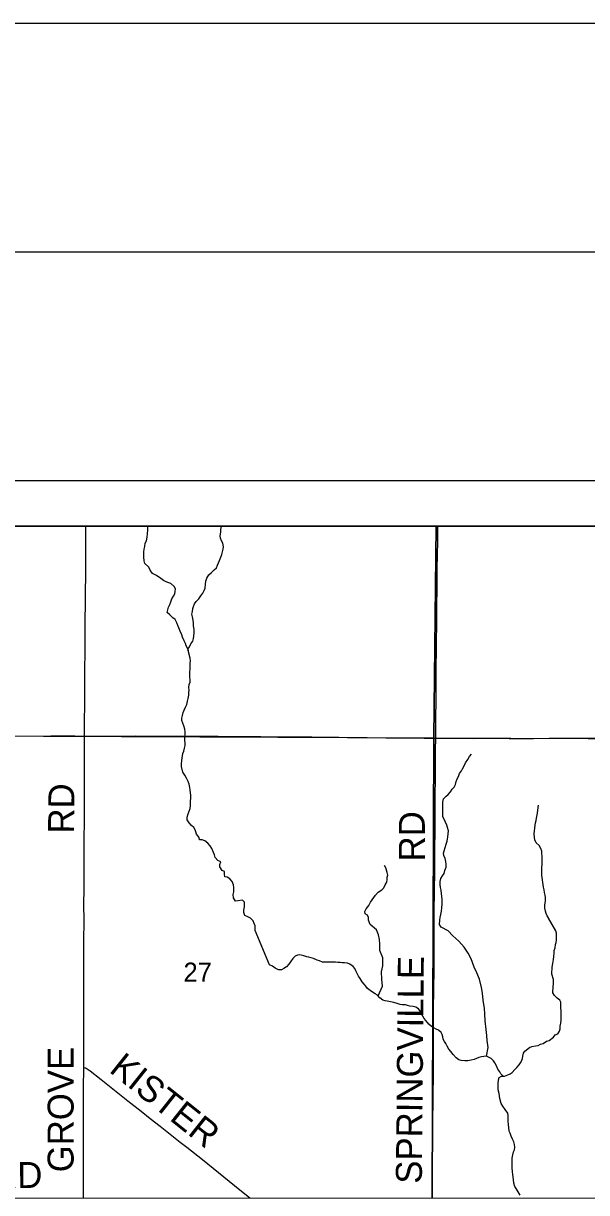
# Model space of a CAD drawing. Extents: x 0 to 34, y 0 to 22.
# Drawn here: x 6.615 to 7.847, y 19.442 to 22 of the extents above; entities that cross this region are included whole.
import ezdxf

# ---------------------------------------------------------------- set-up
doc = ezdxf.new("R2010")
doc.units = 0
for name, color, linetype in [('Default', 7, 'Continuous'), ('GM_X_County_Road', 7, 'Continuous'), ('GM_X_County_Road_Text', 7, 'Continuous'), ('GM_X_Minor_River', 7, 'Continuous'), ('GM_X_Section', 7, 'Continuous'), ('GM_X_Section_Text', 7, 'Continuous'), ('GM_X_Township_Road', 7, 'Continuous'), ('GM_X_Township_Road_Text', 7, 'Continuous'), ('SH_Border', 7, 'Continuous'), ('SH_Cut_Line', 7, 'Continuous'), ('SH_Data', 7, 'Continuous')]:
    doc.layers.add(name, color=color, linetype=linetype)

msp = doc.modelspace()

# ---------------------------------------------------------------- linework, layer by layer
at = {"layer": 'Default'}
msp.add_lwpolyline([(6.4755, 18.4174), (6.6827, 18.4182), (7.4947, 18.4149), (8.508, 18.4199), (8.7888, 18.4255), (8.8212, 18.4259), (8.9, 18.4271), (8.9, 20.9), (2.6032, 20.9)], dxfattribs=at)
for points in [[(7.5179, 20.9), (6.4922, 20.9), (6.4874, 20.4413), (7.5127, 20.4367)], [(8.5341, 20.9), (7.5179, 20.9), (7.5127, 20.4367), (8.5257, 20.4329)]]:
    msp.add_lwpolyline(points, close=True, dxfattribs=at)
at = {"layer": 'GM_X_County_Road'}
for points in [[(6.7486, 20.4407), (6.7487, 20.4682), (6.749, 20.515), (6.7495, 20.5555), (6.7498, 20.655), (6.7499, 20.6735), (6.7503, 20.7045), (6.7505, 20.72), (6.7509, 20.7542), (6.7514, 20.7946), (6.7515, 20.813), (6.7517, 20.8275), (6.7517, 20.8473), (6.7515, 20.8628), (6.7515, 20.8939), (6.7516, 20.9)], [(6.747, 19.7154), (6.747, 19.7232), (6.7474, 19.7542), (6.7472, 19.7698), (6.7471, 19.8029), (6.7471, 19.8471), (6.7473, 19.912), (6.7474, 19.9371), (6.7473, 19.9994), (6.7475, 20.0304), (6.7474, 20.0802), (6.7475, 20.0988), (6.7477, 20.1484), (6.7479, 20.1826), (6.748, 20.2005), (6.7481, 20.2197), (6.7483, 20.2504), (6.7486, 20.2831), (6.7484, 20.3187), (6.7484, 20.3407), (6.7484, 20.3627), (6.7484, 20.3968), (6.7485, 20.4156), (6.7486, 20.4407)], [(6.7466, 19.4306), (6.7466, 19.4363), (6.7466, 19.4747), (6.7467, 19.4996), (6.7467, 19.5338), (6.7467, 19.5647), (6.7465, 19.6145), (6.7467, 19.6702), (6.747, 19.7154)]]:
    msp.add_lwpolyline(points, dxfattribs=at)
at = {"layer": 'GM_X_Minor_River'}
for points in [[(6.9797, 20.6116), (6.9766, 20.6222), (6.9758, 20.6271), (6.9735, 20.6332), (6.9708, 20.6385), (6.9693, 20.6435), (6.9666, 20.6495), (6.9627, 20.6575), (6.9612, 20.6624), (6.9577, 20.6704), (6.955, 20.6776), (6.9524, 20.6829), (6.9504, 20.6886), (6.947, 20.6955), (6.942, 20.6996), (6.9352, 20.706), (6.9294, 20.7113), (6.9305, 20.7167), (6.9324, 20.7228), (6.935, 20.7289), (6.9377, 20.7342), (6.9399, 20.741), (6.9433, 20.7468), (6.9459, 20.7517), (6.947, 20.757), (6.9474, 20.7631), (6.9447, 20.7684), (6.9375, 20.7749), (6.931, 20.7771), (6.926, 20.779), (6.9211, 20.7813), (6.9158, 20.7854), (6.9062, 20.7918), (6.8975, 20.7967), (6.8925, 20.8039), (6.8891, 20.81), (6.8807, 20.8187), (6.8791, 20.8244), (6.8783, 20.832), (6.8783, 20.8392), (6.8786, 20.8442), (6.8794, 20.8495), (6.8805, 20.8556), (6.8816, 20.8628), (6.8838, 20.8682), (6.8853, 20.8758), (6.8864, 20.883), (6.8871, 20.8917), (6.8871, 20.8967), (6.8868, 20.9)], [(6.9797, 20.6116), (6.9743, 20.6309), (6.9784, 20.6359), (6.981, 20.6428), (6.9852, 20.6485), (6.9867, 20.6546), (6.9874, 20.6595), (6.9885, 20.6671), (6.9881, 20.674), (6.9873, 20.6823), (6.9869, 20.6876), (6.9861, 20.6945), (6.9845, 20.7017), (6.9837, 20.7078), (6.9845, 20.7131), (6.9856, 20.7196), (6.9871, 20.7245), (6.9893, 20.7299), (6.9931, 20.7356), (6.9984, 20.7413), (7.0033, 20.7474), (7.0074, 20.7535), (7.0104, 20.7592), (7.0123, 20.7646), (7.0134, 20.7729), (7.0141, 20.7794), (7.0159, 20.7866), (7.0208, 20.7935), (7.0261, 20.7989), (7.0322, 20.8042), (7.0371, 20.8092), (7.0393, 20.8145), (7.042, 20.8198), (7.0442, 20.8252), (7.0468, 20.8324), (7.0487, 20.8377), (7.0517, 20.8499), (7.0528, 20.8549), (7.0508, 20.8628), (7.0482, 20.8682), (7.0462, 20.8735), (7.0451, 20.8788), (7.0465, 20.8872), (7.0469, 20.8925), (7.0484, 20.8993), (7.0486, 20.9)], [(7.1217, 20.0157), (7.1221, 20.0199), (7.1217, 20.0259), (7.1197, 20.0309), (7.1178, 20.0366), (7.1117, 20.0426), (7.106, 20.0453), (7.0995, 20.0483), (7.0968, 20.0547), (7.0972, 20.0597), (7.0987, 20.0673), (7.0986, 20.0772), (7.0944, 20.0821), (7.0849, 20.0805), (7.0789, 20.0797), (7.0743, 20.0866), (7.0739, 20.0945), (7.075, 20.1002), (7.0749, 20.1097), (7.0745, 20.1151), (7.0718, 20.123), (7.0665, 20.1287), (7.0604, 20.1325), (7.0554, 20.1332), (7.0546, 20.1389), (7.0546, 20.1446), (7.0497, 20.1465), (7.0447, 20.1545), (7.0447, 20.1598), (7.0465, 20.1659), (7.0404, 20.1689), (7.0347, 20.175), (7.0332, 20.1807), (7.0305, 20.186), (7.027, 20.1951), (7.0236, 20.2008), (7.0186, 20.2064), (7.0121, 20.2117), (7.0057, 20.214), (7.0004, 20.214), (6.9992, 20.2189), (6.9935, 20.2261), (6.9919, 20.231), (6.9908, 20.236), (6.9877, 20.2409), (6.9824, 20.2454), (6.9774, 20.2511), (6.9732, 20.2576), (6.9732, 20.2636), (6.9754, 20.2709), (6.9799, 20.2823), (6.9802, 20.2888), (6.9806, 20.2975), (6.9809, 20.3055), (6.9809, 20.3108), (6.9805, 20.3173), (6.9797, 20.3226), (6.9789, 20.3283), (6.9773, 20.3359), (6.975, 20.3416), (6.9716, 20.3484), (6.9677, 20.3556), (6.9639, 20.3617), (6.9608, 20.3746), (6.9608, 20.3799), (6.9611, 20.3872), (6.9626, 20.3978), (6.9633, 20.4028), (6.9656, 20.4081), (6.9674, 20.4142), (6.9689, 20.4199), (6.9689, 20.4248), (6.9681, 20.4324), (6.9677, 20.4385), (6.9684, 20.4454), (6.9684, 20.4503), (6.968, 20.456), (6.9657, 20.4632), (6.9618, 20.4746), (6.9618, 20.4803), (6.9629, 20.486), (6.9647, 20.4921), (6.9666, 20.4978), (6.9696, 20.5039), (6.9722, 20.51), (6.9741, 20.5169), (6.9756, 20.5233), (6.9771, 20.5306), (6.977, 20.5363), (6.9774, 20.5416), (6.977, 20.5469), (6.9777, 20.5538), (6.9796, 20.5587), (6.9795, 20.5637), (6.9791, 20.5694), (6.9791, 20.5812), (6.9794, 20.5869), (6.9794, 20.5945), (6.9797, 20.6002), (6.9805, 20.6055), (6.9797, 20.6116)], [(7.5442, 20.0149), (7.5291, 20.023), (7.5254, 20.0289), (7.5258, 20.0384), (7.5269, 20.0438), (7.528, 20.0506), (7.5295, 20.0575), (7.5302, 20.0647), (7.5309, 20.0734), (7.5308, 20.0829), (7.53, 20.0905), (7.5296, 20.0955), (7.5288, 20.1035), (7.5277, 20.1095), (7.5265, 20.116), (7.5268, 20.1225), (7.5283, 20.1289), (7.5317, 20.135), (7.5355, 20.14), (7.5366, 20.1465), (7.5396, 20.1537), (7.5399, 20.1609), (7.5391, 20.1666), (7.5376, 20.1727), (7.5349, 20.1792), (7.5337, 20.1845), (7.5352, 20.1898), (7.5378, 20.197), (7.5401, 20.2043), (7.5416, 20.2107), (7.5434, 20.2203), (7.5441, 20.2267), (7.5445, 20.2336), (7.5425, 20.2408), (7.5414, 20.2461), (7.5379, 20.2537), (7.5352, 20.2594), (7.5322, 20.2643), (7.5321, 20.2708), (7.5325, 20.2757), (7.5328, 20.281), (7.5328, 20.2959), (7.5339, 20.3035), (7.5395, 20.3096), (7.5444, 20.313), (7.5493, 20.3188), (7.5527, 20.3245), (7.5572, 20.3294), (7.5603, 20.3352), (7.5617, 20.3416), (7.564, 20.3473), (7.567, 20.3523), (7.5692, 20.3591), (7.5734, 20.3645), (7.5753, 20.3694), (7.5794, 20.3759), (7.582, 20.382), (7.5869, 20.3893), (7.5911, 20.3961), (7.5948, 20.4015)], [(7.7634, 20.0426), (7.7633, 20.0429), (7.7606, 20.0479), (7.7583, 20.0528), (7.7568, 20.0581), (7.7556, 20.0646), (7.7559, 20.0718), (7.757, 20.0798), (7.7574, 20.0874), (7.7566, 20.0931), (7.755, 20.0988), (7.7539, 20.1045), (7.7527, 20.1106), (7.7511, 20.1205), (7.7507, 20.1262), (7.7496, 20.1311), (7.7488, 20.1368), (7.7487, 20.1474), (7.7491, 20.1535), (7.7494, 20.16), (7.7498, 20.1672), (7.7497, 20.1782), (7.7493, 20.1839), (7.7493, 20.1893), (7.747, 20.1946), (7.7431, 20.2014), (7.7363, 20.2075), (7.7336, 20.2139), (7.7328, 20.2188), (7.7324, 20.2272), (7.7327, 20.2333), (7.7334, 20.2394), (7.7345, 20.2458), (7.7353, 20.2508), (7.7364, 20.2561), (7.7371, 20.2611), (7.7397, 20.2721), (7.7412, 20.2843), (7.7419, 20.29)], [(7.3733, 20.0284), (7.3698, 20.0381), (7.3698, 20.0438), (7.3675, 20.0491), (7.3625, 20.0518), (7.3621, 20.0571), (7.3647, 20.0628), (7.3704, 20.0704), (7.3745, 20.0777), (7.3775, 20.0826), (7.3817, 20.0876), (7.3854, 20.0925), (7.3911, 20.0994), (7.3987, 20.1048), (7.4036, 20.109), (7.4062, 20.1151), (7.4096, 20.1215), (7.4107, 20.1269), (7.411, 20.1318), (7.4118, 20.1368), (7.4106, 20.1425), (7.4091, 20.1474), (7.4079, 20.1527), (7.4045, 20.158)], [(7.7762, 19.9659), (7.7762, 19.9716), (7.7781, 19.9777), (7.7792, 19.9845), (7.7807, 19.9894), (7.7811, 19.9952), (7.781, 20.0016), (7.7814, 20.0096), (7.7795, 20.0145), (7.7634, 20.0426)], [(7.6645, 19.6969), (7.6596, 19.7017), (7.657, 19.7062), (7.6531, 19.7123), (7.6489, 19.7207), (7.6462, 19.7256), (7.6432, 19.7306), (7.6382, 19.7351), (7.6336, 19.7378), (7.6283, 19.7408), (7.6225, 19.7397), (7.6172, 19.7389), (7.6111, 19.7378), (7.6061, 19.7355), (7.6008, 19.7336), (7.5943, 19.7317), (7.5871, 19.7306), (7.5806, 19.7302), (7.5729, 19.7314), (7.5676, 19.7325), (7.5619, 19.7367), (7.5554, 19.7439), (7.55, 19.7504), (7.5458, 19.7561), (7.542, 19.7622), (7.5389, 19.7679), (7.5358, 19.7725), (7.5335, 19.7778), (7.5324, 19.7831), (7.5312, 19.7877), (7.5285, 19.7926), (7.5232, 19.7972), (7.5182, 19.7995), (7.5125, 19.8025), (7.5075, 19.8052), (7.5021, 19.8105), (7.4956, 19.8185), (7.4914, 19.8231), (7.4884, 19.828), (7.4861, 19.8329), (7.4845, 19.8375), (7.4792, 19.8444), (7.4734, 19.8474), (7.4673, 19.8489), (7.4605, 19.8501), (7.4555, 19.8516), (7.4505, 19.8527), (7.4437, 19.8531), (7.4391, 19.8539), (7.4326, 19.8558), (7.4249, 19.8581), (7.4177, 19.8592), (7.4108, 19.8607), (7.4062, 19.8619), (7.4013, 19.8634), (7.3948, 19.868), (7.3898, 19.8741), (7.3841, 19.8771), (7.3787, 19.8805), (7.3737, 19.884), (7.368, 19.8889), (7.3638, 19.8939), (7.3607, 19.8984), (7.3561, 19.9034), (7.3519, 19.9102), (7.3481, 19.9159), (7.345, 19.9212), (7.342, 19.9269), (7.34, 19.9323), (7.3362, 19.9368), (7.329, 19.9418), (7.3236, 19.9437), (7.3175, 19.9445), (7.3125, 19.9445), (7.308, 19.9456), (7.3026, 19.9456), (7.298, 19.9464), (7.2889, 19.946), (7.2828, 19.9464), (7.269, 19.9464), (7.2629, 19.949), (7.2572, 19.9506), (7.2492, 19.954), (7.2396, 19.957), (7.2347, 19.9578), (7.2282, 19.9597), (7.2198, 19.962), (7.2148, 19.9616), (7.2095, 19.959), (7.2045, 19.9544), (7.1992, 19.9468), (7.1954, 19.9419), (7.1901, 19.9358), (7.1847, 19.932), (7.1794, 19.9297), (7.1733, 19.9293), (7.1656, 19.9331), (7.1595, 19.9377), (7.1534, 19.9407), (7.1217, 20.0157)], [(7.3908, 19.8729), (7.4004, 19.8937), (7.3992, 19.9089), (7.3984, 19.9252), (7.4013, 19.9385), (7.4009, 19.9556), (7.3948, 19.9719), (7.3943, 19.9855), (7.3939, 19.9958), (7.3916, 20.0057), (7.3874, 20.017), (7.3733, 20.0284)], [(7.6283, 19.7408), (7.6316, 19.7597), (7.6296, 19.7745), (7.6284, 19.7859), (7.6269, 19.7988), (7.6253, 19.8182), (7.6245, 19.8334), (7.6233, 19.8447), (7.6209, 19.8633), (7.619, 19.8785), (7.617, 19.8906), (7.6128, 19.9092), (7.6071, 19.9232), (7.6013, 19.9354), (7.5945, 19.9536), (7.588, 19.9661), (7.5788, 19.9793), (7.5678, 19.9922), (7.5545, 20.0035), (7.5442, 20.0149)], [(7.7019, 19.4366), (7.6969, 19.4434), (7.6931, 19.4507), (7.69, 19.4552), (7.6877, 19.4624), (7.6869, 19.4704), (7.6857, 19.4815), (7.685, 19.4872), (7.6842, 19.4967), (7.6838, 19.5054), (7.6838, 19.5111), (7.6841, 19.5172), (7.6856, 19.5248), (7.6871, 19.5309), (7.689, 19.5358), (7.6898, 19.5415), (7.6894, 19.5476), (7.6875, 19.5533), (7.6852, 19.5587), (7.6821, 19.5655), (7.6798, 19.572), (7.6775, 19.5765), (7.6767, 19.5845), (7.6759, 19.591), (7.6755, 19.5982), (7.6755, 19.6104), (7.6743, 19.6161), (7.6686, 19.6237), (7.6636, 19.6309), (7.6598, 19.637), (7.6575, 19.648), (7.6555, 19.6587), (7.6536, 19.6667), (7.6532, 19.672), (7.6532, 19.6807), (7.6543, 19.6891), (7.6555, 19.6937), (7.6608, 19.6971), (7.6673, 19.6967), (7.6749, 19.6997), (7.6795, 19.7016), (7.6844, 19.7051), (7.6898, 19.7111), (7.6947, 19.7161), (7.6993, 19.7214), (7.7038, 19.7282), (7.7069, 19.7355), (7.7076, 19.7408), (7.7088, 19.7469), (7.7122, 19.7514), (7.7217, 19.7594), (7.727, 19.7617), (7.7351, 19.7632), (7.7408, 19.764), (7.7461, 19.7666), (7.7522, 19.7681), (7.7595, 19.7731), (7.7648, 19.775), (7.7743, 19.7818), (7.7785, 19.7871), (7.7838, 19.7894), (7.788, 19.7955), (7.7888, 19.8004), (7.7895, 19.8062), (7.7903, 19.8126), (7.791, 19.8191), (7.7914, 19.8263), (7.791, 19.8335), (7.7914, 19.8408), (7.7906, 19.8457), (7.7905, 19.8586), (7.7882, 19.8632), (7.7825, 19.8678), (7.7764, 19.8731), (7.7733, 19.8788), (7.7733, 19.8834), (7.7741, 19.8883), (7.7741, 19.8932), (7.7744, 19.8978), (7.7744, 19.9081), (7.7709, 19.9199), (7.7709, 19.9256), (7.7713, 19.9301), (7.772, 19.9351), (7.7728, 19.9434), (7.7747, 19.9518), (7.7754, 19.9583), (7.7762, 19.9659)]]:
    msp.add_lwpolyline(points, dxfattribs=at)
at = {"layer": 'GM_X_Section'}
for points in [[(6.4874, 20.4413), (7.5127, 20.4367), (7.5091, 19.4296), (6.4824, 19.4291)], [(7.5127, 20.4367), (8.5257, 20.4329), (8.5218, 19.4295), (7.5091, 19.4296)]]:
    msp.add_lwpolyline(points, close=True, dxfattribs=at)
at = {"layer": 'GM_X_Township_Road'}
for points in [[(7.5169, 20.4363), (7.5173, 20.4701), (7.5176, 20.5291), (7.5182, 20.5819), (7.5186, 20.6378), (7.5191, 20.6968), (7.5193, 20.7216), (7.5199, 20.7682), (7.5203, 20.7993), (7.5203, 20.8148), (7.5207, 20.8301), (7.5211, 20.8425), (7.5214, 20.8611), (7.5214, 20.9)], [(6.5908, 20.4409), (6.6746, 20.4412), (6.6932, 20.4412), (6.7274, 20.441), (6.7486, 20.4407)], [(6.7486, 20.4407), (6.7554, 20.4406), (6.7833, 20.4407), (6.8113, 20.4409), (6.8299, 20.4409), (6.8609, 20.441), (6.8951, 20.4409), (6.9292, 20.4409), (6.9602, 20.4408), (6.9882, 20.4406), (7.041, 20.4405), (7.097, 20.4401), (7.1342, 20.4397), (7.1839, 20.4391), (7.2149, 20.4388), (7.246, 20.4388), (7.277, 20.4387), (7.305, 20.4382), (7.3236, 20.438), (7.3671, 20.4377), (7.4075, 20.4371), (7.4355, 20.4367), (7.4914, 20.4364), (7.5169, 20.4363)], [(7.509, 19.4382), (7.509, 19.4568), (7.509, 19.4745), (7.5091, 19.4854), (7.5092, 19.4997), (7.5099, 19.5164), (7.5102, 19.536), (7.5106, 19.5702), (7.5105, 19.5917), (7.5107, 19.6041), (7.511, 19.6382), (7.5117, 19.7159), (7.5119, 19.75), (7.512, 19.7686), (7.5121, 19.7903), (7.5121, 19.8059), (7.5121, 19.8245), (7.5121, 19.843), (7.5122, 19.8554), (7.5124, 19.874), (7.5132, 19.9423), (7.5134, 19.9827), (7.5134, 19.9982), (7.5133, 20.0355), (7.5134, 20.0541), (7.5142, 20.1037), (7.5147, 20.1441), (7.5153, 20.1937), (7.5155, 20.2341), (7.5155, 20.262), (7.5156, 20.2744), (7.5157, 20.2993), (7.516, 20.3179), (7.5162, 20.3397), (7.5163, 20.3645), (7.5164, 20.38), (7.5167, 20.4142), (7.5169, 20.4328), (7.5169, 20.4363)], [(7.5169, 20.4363), (7.5536, 20.436), (7.6002, 20.4357), (7.6375, 20.4359), (7.6779, 20.4358), (7.7307, 20.4358), (7.7649, 20.4359), (7.8115, 20.4361), (7.8426, 20.4362), (7.883, 20.4363), (7.9172, 20.4362), (7.942, 20.4362), (7.9637, 20.4362), (7.9824, 20.4361), (8.0103, 20.4359), (8.029, 20.4358)], [(6.747, 19.7154), (6.7493, 19.7153), (6.7504, 19.7153), (6.752, 19.7146), (6.7544, 19.7131), (6.7606, 19.7085), (6.785, 19.6893), (6.8216, 19.6605), (6.8435, 19.6431), (6.8727, 19.62), (6.8922, 19.6045), (6.9142, 19.5873), (6.9579, 19.5526), (6.9726, 19.5411), (7.0064, 19.5142), (7.0766, 19.4579), (7.1105, 19.4307)]]:
    msp.add_lwpolyline(points, dxfattribs=at)
at = {"layer": 'SH_Border'}
msp.add_lwpolyline([(1.5, 21.5), (33.5, 21.5), (33.5, 0.5), (1.5, 0.5)], close=True, dxfattribs=at)
at = {"layer": 'SH_Cut_Line'}
msp.add_lwpolyline([(0, 0), (34, 0), (34, 22), (0, 22)], close=True, dxfattribs=at)
msp.add_lwpolyline([(8.9, 14.3696), (8.9, 20.9), (2.6032, 20.9)], dxfattribs=at)
at = {"layer": 'SH_Data'}
for p, q in [((2, 21), (9, 21)), ((2.1, 20.9), (8.9, 20.9))]:
    msp.add_line(p, q, dxfattribs=at)

# ---------------------------------------------------------------- texts
at = {"layer": 'GM_X_County_Road_Text'}
for s, rotation, p in [('RD', 89.5099, (6.7256, 20.2274)), ('GROVE', 90, (6.7247, 19.4865))]:
    msp.add_text(s, height=0.05682, rotation=rotation, dxfattribs=at).set_placement(p)
at = {"layer": 'GM_X_Section_Text'}
msp.add_text('27', height=0.04186, rotation=0, dxfattribs=at).set_placement((6.965, 19.9034))
at = {"layer": 'GM_X_Township_Road_Text'}
for s, height, rotation, p in [('RD', 0.05682, 90, (7.4931, 20.1667)), ('SPRINGVILLE', 0.056818, 89.4704, (7.4864, 19.4613)), ('KISTER', 0.05682, 321.459, (6.8002, 19.7075)), ('RD', 0.05682, 0.4936, (6.5469, 19.4515))]:
    msp.add_text(s, height=height, rotation=rotation, dxfattribs=at).set_placement(p)

doc.saveas('drawing.dxf')
